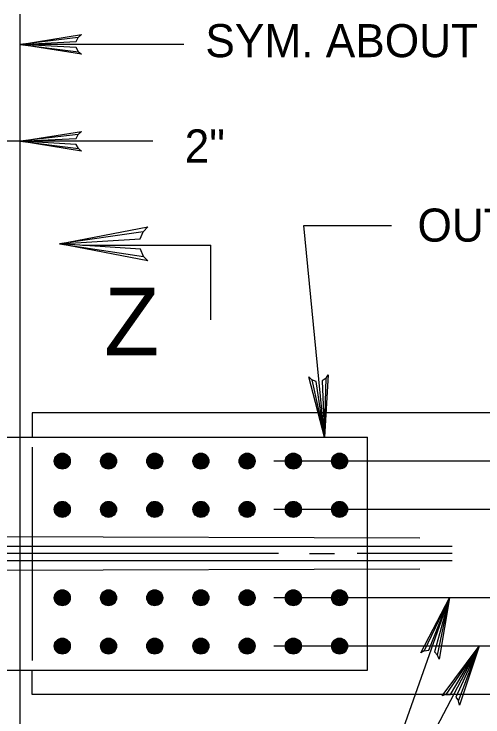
# Model space of a CAD drawing. Extents: x 638466 to 639375, y 297808 to 298996.
# Drawn here: x 638967.9 to 639013.8, y 298148.9 to 298217.7 of the extents above; entities that cross this region are included whole.
import ezdxf

# ---------------------------------------------------------------- set-up
doc = ezdxf.new("R2010")
doc.units = 0
for name, color, linetype in [('1', 7, 'Continuous'), ('2', 7, 'Continuous'), ('4', 7, 'Continuous')]:
    doc.layers.add(name, color=color, linetype=linetype)

msp = doc.modelspace()

# ---------------------------------------------------------------- linework, layer by layer
at = {"layer": '1'}
for points in [[(638974.195, 298214.016), (638973.983, 298214.43), (638968.473, 298214.736), (638974.195, 298214.016), (638974.487, 298213.764), (638968.473, 298214.736), (638973.977, 298215.006), (638974.179, 298215.415), (638968.473, 298214.736), (638974.487, 298215.69), (638974.179, 298215.415)], [(638974.195, 298204.523), (638973.983, 298204.935), (638968.473, 298205.241), (638974.195, 298204.523), (638974.487, 298204.271), (638968.473, 298205.241), (638973.977, 298205.511), (638974.179, 298205.92), (638968.473, 298205.241), (638974.487, 298206.195), (638974.179, 298205.92)], [(638980.565, 298193.966), (638980.259, 298194.682), (638972.327, 298195.208), (638980.565, 298193.966), (638980.983, 298193.532), (638972.327, 298195.208), (638980.25, 298195.674), (638980.542, 298196.383), (638972.327, 298195.208), (638980.983, 298196.86), (638980.542, 298196.383)], [(638998.452, 298182.043), (638998.058, 298181.791), (638998.286, 298176.279), (638998.452, 298182.043), (638998.673, 298182.358), (638998.286, 298176.279), (638997.485, 298181.733), (638997.059, 298181.893), (638998.286, 298176.279), (638996.758, 298182.174), (638997.059, 298181.893)], [(639008.053, 298155.338), (639008.514, 298155.408), (639010.555, 298160.533), (639008.053, 298155.338), (639007.722, 298155.14), (639010.555, 298160.533), (639009.061, 298155.228), (639009.385, 298154.906), (639010.555, 298160.533), (639009.547, 298154.526), (639009.385, 298154.906)], [(639010.172, 298151.063), (639010.64, 298151.061), (639013.446, 298155.811), (639010.172, 298151.063), (639009.817, 298150.919), (639013.446, 298155.811), (639011.153, 298150.8), (639011.423, 298150.433), (639013.446, 298155.811), (639011.525, 298150.03), (639011.423, 298150.433)]]:
    msp.add_lwpolyline(points, dxfattribs=at)
at = {"layer": '2'}
for p, q in [((638968.473, 298137.466), (638968.473, 298217.701)), ((638969.654, 298178.641), (638969.654, 298176.279)), ((639039.337, 298178.641), (638969.654, 298178.641)), ((638934.694, 298176.279), (639002.527, 298176.279)), ((639002.527, 298153.441), (639002.527, 298176.279)), ((638969.654, 298175.302), (638969.654, 298154.409)), ((639007.648, 298166.377), (638929.301, 298166.624)), ((639010.8, 298165.573), (638925.401, 298165.573)), ((638993.799, 298164.865), (638925.401, 298164.865)), ((638996.821, 298164.865), (638999.294, 298164.865)), ((639010.8, 298164.865), (639001.492, 298164.865)), ((639010.8, 298164.156), (638925.401, 298164.156)), ((639007.648, 298163.352), (638929.301, 298163.103)), ((638934.532, 298153.441), (639002.527, 298153.441)), ((638969.654, 298151.079), (638969.654, 298153.441)), ((639039.337, 298151.079), (638969.654, 298151.079))]:
    msp.add_line(p, q, dxfattribs=at)
for centre, radius in [((638972.612, 298173.919), 0.783), ((638972.612, 298173.919), 0.727), ((638977.138, 298173.919), 0.783), ((638977.138, 298173.919), 0.727), ((638981.665, 298173.919), 0.783), ((638981.665, 298173.919), 0.727), ((638986.191, 298173.919), 0.783), ((638986.191, 298173.919), 0.727), ((638990.721, 298173.919), 0.783), ((638990.721, 298173.919), 0.727), ((638995.248, 298173.919), 0.783), ((638995.248, 298173.919), 0.727), ((638999.774, 298173.919), 0.783), ((638999.774, 298173.919), 0.727), ((638972.612, 298173.919), 0.672), ((638972.612, 298173.919), 0.616), ((638972.612, 298173.919), 0.561), ((638972.612, 298173.919), 0.505), ((638972.612, 298173.919), 0.449), ((638972.612, 298173.919), 0.394), ((638972.612, 298173.919), 0.338), ((638972.612, 298173.919), 0.283), ((638972.612, 298173.919), 0.227), ((638972.612, 298173.919), 0.171), ((638972.612, 298173.919), 0.116), ((638972.612, 298173.919), 0.0601), ((638977.138, 298173.919), 0.672), ((638977.138, 298173.919), 0.616), ((638977.138, 298173.919), 0.561), ((638977.138, 298173.919), 0.505), ((638977.138, 298173.919), 0.449), ((638977.138, 298173.919), 0.394), ((638977.138, 298173.919), 0.338), ((638977.138, 298173.919), 0.283), ((638977.138, 298173.919), 0.227), ((638977.138, 298173.919), 0.171), ((638977.138, 298173.919), 0.116), ((638977.138, 298173.919), 0.0601), ((638981.665, 298173.919), 0.672), ((638981.665, 298173.919), 0.616), ((638981.665, 298173.919), 0.561), ((638981.665, 298173.919), 0.505), ((638981.665, 298173.919), 0.449), ((638981.665, 298173.919), 0.394), ((638981.665, 298173.919), 0.338), ((638981.665, 298173.919), 0.283), ((638981.665, 298173.919), 0.227), ((638981.665, 298173.919), 0.171), ((638981.665, 298173.919), 0.116), ((638981.665, 298173.919), 0.0601), ((638986.191, 298173.919), 0.672), ((638986.191, 298173.919), 0.616), ((638986.191, 298173.919), 0.561), ((638986.191, 298173.919), 0.505), ((638986.191, 298173.919), 0.449), ((638986.191, 298173.919), 0.394), ((638986.191, 298173.919), 0.338), ((638986.191, 298173.919), 0.283), ((638986.191, 298173.919), 0.227), ((638986.191, 298173.919), 0.171), ((638986.191, 298173.919), 0.116), ((638986.191, 298173.919), 0.0601), ((638990.721, 298173.919), 0.672), ((638990.721, 298173.919), 0.616), ((638990.721, 298173.919), 0.561), ((638990.721, 298173.919), 0.505), ((638990.721, 298173.919), 0.449), ((638990.721, 298173.919), 0.394), ((638990.721, 298173.919), 0.338), ((638990.721, 298173.919), 0.283), ((638990.721, 298173.919), 0.227), ((638990.721, 298173.919), 0.171), ((638990.721, 298173.919), 0.116), ((638990.721, 298173.919), 0.0601), ((638995.248, 298173.919), 0.672), ((638995.248, 298173.919), 0.616), ((638995.248, 298173.919), 0.561), ((638995.248, 298173.919), 0.505), ((638995.248, 298173.919), 0.449), ((638995.248, 298173.919), 0.394), ((638995.248, 298173.919), 0.338), ((638995.248, 298173.919), 0.283), ((638995.248, 298173.919), 0.227), ((638995.248, 298173.919), 0.171), ((638995.248, 298173.919), 0.116), ((638995.248, 298173.919), 0.0601), ((638999.774, 298173.919), 0.672), ((638999.774, 298173.919), 0.616), ((638999.774, 298173.919), 0.561), ((638999.774, 298173.919), 0.505), ((638999.774, 298173.919), 0.449), ((638999.774, 298173.919), 0.394), ((638999.774, 298173.919), 0.338), ((638999.774, 298173.919), 0.283), ((638999.774, 298173.919), 0.227), ((638999.774, 298173.919), 0.171), ((638999.774, 298173.919), 0.116), ((638999.774, 298173.919), 0.0601), ((638972.612, 298169.197), 0.783), ((638972.612, 298169.197), 0.727), ((638972.612, 298169.197), 0.672), ((638972.612, 298169.197), 0.616), ((638977.138, 298169.197), 0.783), ((638977.138, 298169.197), 0.727), ((638977.138, 298169.197), 0.672), ((638977.138, 298169.197), 0.616), ((638981.665, 298169.197), 0.783), ((638981.665, 298169.197), 0.727), ((638981.665, 298169.197), 0.672), ((638981.665, 298169.197), 0.616), ((638986.191, 298169.197), 0.783), ((638986.191, 298169.197), 0.727), ((638986.191, 298169.197), 0.672), ((638986.191, 298169.197), 0.616), ((638990.721, 298169.197), 0.783), ((638990.721, 298169.197), 0.727), ((638990.721, 298169.197), 0.672), ((638990.721, 298169.197), 0.616), ((638995.248, 298169.197), 0.783), ((638995.248, 298169.197), 0.727), ((638995.248, 298169.197), 0.672), ((638995.248, 298169.197), 0.616), ((638999.774, 298169.197), 0.783), ((638999.774, 298169.197), 0.727), ((638999.774, 298169.197), 0.672), ((638999.774, 298169.197), 0.616), ((638972.612, 298169.197), 0.561), ((638972.612, 298169.197), 0.505), ((638972.612, 298169.197), 0.449), ((638972.612, 298169.197), 0.394), ((638972.612, 298169.197), 0.338), ((638972.612, 298169.197), 0.283), ((638972.612, 298169.197), 0.227), ((638972.612, 298169.197), 0.171), ((638972.612, 298169.197), 0.116), ((638972.612, 298169.197), 0.0601), ((638977.138, 298169.197), 0.561), ((638977.138, 298169.197), 0.505), ((638977.138, 298169.197), 0.449), ((638977.138, 298169.197), 0.394), ((638977.138, 298169.197), 0.338), ((638977.138, 298169.197), 0.283), ((638977.138, 298169.197), 0.227), ((638977.138, 298169.197), 0.171), ((638977.138, 298169.197), 0.116), ((638977.138, 298169.197), 0.0601), ((638981.665, 298169.197), 0.561), ((638981.665, 298169.197), 0.505), ((638981.665, 298169.197), 0.449), ((638981.665, 298169.197), 0.394), ((638981.665, 298169.197), 0.338), ((638981.665, 298169.197), 0.283), ((638981.665, 298169.197), 0.227), ((638981.665, 298169.197), 0.171), ((638981.665, 298169.197), 0.116), ((638981.665, 298169.197), 0.0601), ((638986.191, 298169.197), 0.561), ((638986.191, 298169.197), 0.505), ((638986.191, 298169.197), 0.449), ((638986.191, 298169.197), 0.394), ((638986.191, 298169.197), 0.338), ((638986.191, 298169.197), 0.283), ((638986.191, 298169.197), 0.227), ((638986.191, 298169.197), 0.171), ((638986.191, 298169.197), 0.116), ((638986.191, 298169.197), 0.0601), ((638990.721, 298169.197), 0.561), ((638990.721, 298169.197), 0.505), ((638990.721, 298169.197), 0.449), ((638990.721, 298169.197), 0.394), ((638990.721, 298169.197), 0.338), ((638990.721, 298169.197), 0.283), ((638990.721, 298169.197), 0.227), ((638990.721, 298169.197), 0.171), ((638990.721, 298169.197), 0.116), ((638990.721, 298169.197), 0.0601), ((638995.248, 298169.197), 0.561), ((638995.248, 298169.197), 0.505), ((638995.248, 298169.197), 0.449), ((638995.248, 298169.197), 0.394), ((638995.248, 298169.197), 0.338), ((638995.248, 298169.197), 0.283), ((638995.248, 298169.197), 0.227), ((638995.248, 298169.197), 0.171), ((638995.248, 298169.197), 0.116), ((638995.248, 298169.197), 0.0601), ((638999.774, 298169.197), 0.561), ((638999.774, 298169.197), 0.505), ((638999.774, 298169.197), 0.449), ((638999.774, 298169.197), 0.394), ((638999.774, 298169.197), 0.338), ((638999.774, 298169.197), 0.283), ((638999.774, 298169.197), 0.227), ((638999.774, 298169.197), 0.171), ((638999.774, 298169.197), 0.116), ((638999.774, 298169.197), 0.0601), ((638972.612, 298160.533), 0.783), ((638972.612, 298160.533), 0.727), ((638972.612, 298160.533), 0.672), ((638972.612, 298160.533), 0.616), ((638972.612, 298160.533), 0.561), ((638972.612, 298160.533), 0.505), ((638972.612, 298160.533), 0.449), ((638972.612, 298160.533), 0.394), ((638972.612, 298160.533), 0.338), ((638977.138, 298160.533), 0.783), ((638977.138, 298160.533), 0.727), ((638977.138, 298160.533), 0.672), ((638977.138, 298160.533), 0.616), ((638977.138, 298160.533), 0.561), ((638977.138, 298160.533), 0.505), ((638977.138, 298160.533), 0.449), ((638977.138, 298160.533), 0.394), ((638977.138, 298160.533), 0.338), ((638981.665, 298160.533), 0.783), ((638981.665, 298160.533), 0.727), ((638981.665, 298160.533), 0.672), ((638981.665, 298160.533), 0.616), ((638981.665, 298160.533), 0.561), ((638981.665, 298160.533), 0.505), ((638981.665, 298160.533), 0.449), ((638981.665, 298160.533), 0.394), ((638981.665, 298160.533), 0.338), ((638986.191, 298160.533), 0.783), ((638986.191, 298160.533), 0.727), ((638986.191, 298160.533), 0.672), ((638986.191, 298160.533), 0.616), ((638986.191, 298160.533), 0.561), ((638986.191, 298160.533), 0.505), ((638986.191, 298160.533), 0.449), ((638986.191, 298160.533), 0.394), ((638986.191, 298160.533), 0.338), ((638990.721, 298160.533), 0.783), ((638990.721, 298160.533), 0.727), ((638990.721, 298160.533), 0.672), ((638990.721, 298160.533), 0.616), ((638990.721, 298160.533), 0.561), ((638990.721, 298160.533), 0.505), ((638990.721, 298160.533), 0.449), ((638990.721, 298160.533), 0.394), ((638990.721, 298160.533), 0.338), ((638995.248, 298160.533), 0.783), ((638995.248, 298160.533), 0.727), ((638995.248, 298160.533), 0.672), ((638995.248, 298160.533), 0.616), ((638995.248, 298160.533), 0.561), ((638995.248, 298160.533), 0.505), ((638995.248, 298160.533), 0.449), ((638995.248, 298160.533), 0.394), ((638995.248, 298160.533), 0.338), ((638999.774, 298160.533), 0.783), ((638999.774, 298160.533), 0.727), ((638999.774, 298160.533), 0.672), ((638999.774, 298160.533), 0.616), ((638999.774, 298160.533), 0.561), ((638999.774, 298160.533), 0.505), ((638999.774, 298160.533), 0.449), ((638999.774, 298160.533), 0.394), ((638999.774, 298160.533), 0.338), ((638972.612, 298160.533), 0.283), ((638972.612, 298160.533), 0.227), ((638972.612, 298160.533), 0.171), ((638972.612, 298160.533), 0.116), ((638972.612, 298160.533), 0.0601), ((638977.138, 298160.533), 0.283), ((638977.138, 298160.533), 0.227), ((638977.138, 298160.533), 0.171), ((638977.138, 298160.533), 0.116), ((638977.138, 298160.533), 0.0601), ((638981.665, 298160.533), 0.283), ((638981.665, 298160.533), 0.227), ((638981.665, 298160.533), 0.171), ((638981.665, 298160.533), 0.116), ((638981.665, 298160.533), 0.0601), ((638986.191, 298160.533), 0.283), ((638986.191, 298160.533), 0.227), ((638986.191, 298160.533), 0.171), ((638986.191, 298160.533), 0.116), ((638986.191, 298160.533), 0.0601), ((638990.721, 298160.533), 0.283), ((638990.721, 298160.533), 0.227), ((638990.721, 298160.533), 0.171), ((638990.721, 298160.533), 0.116), ((638990.721, 298160.533), 0.0601), ((638995.248, 298160.533), 0.283), ((638995.248, 298160.533), 0.227), ((638995.248, 298160.533), 0.171), ((638995.248, 298160.533), 0.116), ((638995.248, 298160.533), 0.0601), ((638999.774, 298160.533), 0.283), ((638999.774, 298160.533), 0.227), ((638999.774, 298160.533), 0.171), ((638999.774, 298160.533), 0.116), ((638999.774, 298160.533), 0.0601), ((638972.612, 298155.811), 0.783), ((638972.612, 298155.811), 0.727), ((638972.612, 298155.811), 0.672), ((638972.612, 298155.811), 0.616), ((638972.612, 298155.811), 0.561), ((638972.612, 298155.811), 0.505), ((638972.612, 298155.811), 0.449), ((638972.612, 298155.811), 0.394), ((638972.612, 298155.811), 0.338), ((638972.612, 298155.811), 0.283), ((638972.612, 298155.811), 0.227), ((638977.138, 298155.811), 0.783), ((638977.138, 298155.811), 0.727), ((638977.138, 298155.811), 0.672), ((638977.138, 298155.811), 0.616), ((638977.138, 298155.811), 0.561), ((638977.138, 298155.811), 0.505), ((638977.138, 298155.811), 0.449), ((638977.138, 298155.811), 0.394), ((638977.138, 298155.811), 0.338), ((638977.138, 298155.811), 0.283), ((638977.138, 298155.811), 0.227), ((638981.665, 298155.811), 0.783), ((638981.665, 298155.811), 0.727), ((638981.665, 298155.811), 0.672), ((638981.665, 298155.811), 0.616), ((638981.665, 298155.811), 0.561), ((638981.665, 298155.811), 0.505), ((638981.665, 298155.811), 0.449), ((638981.665, 298155.811), 0.394), ((638981.665, 298155.811), 0.338), ((638981.665, 298155.811), 0.283), ((638981.665, 298155.811), 0.227), ((638986.191, 298155.811), 0.783), ((638986.191, 298155.811), 0.727), ((638986.191, 298155.811), 0.672), ((638986.191, 298155.811), 0.616), ((638986.191, 298155.811), 0.561), ((638986.191, 298155.811), 0.505), ((638986.191, 298155.811), 0.449), ((638986.191, 298155.811), 0.394), ((638986.191, 298155.811), 0.338), ((638986.191, 298155.811), 0.283), ((638986.191, 298155.811), 0.227), ((638990.721, 298155.811), 0.783), ((638990.721, 298155.811), 0.727), ((638990.721, 298155.811), 0.672), ((638990.721, 298155.811), 0.616), ((638990.721, 298155.811), 0.561), ((638990.721, 298155.811), 0.505), ((638990.721, 298155.811), 0.449), ((638990.721, 298155.811), 0.394), ((638990.721, 298155.811), 0.338), ((638990.721, 298155.811), 0.283), ((638990.721, 298155.811), 0.227), ((638995.248, 298155.811), 0.783), ((638995.248, 298155.811), 0.727), ((638995.248, 298155.811), 0.672), ((638995.248, 298155.811), 0.616), ((638995.248, 298155.811), 0.561), ((638995.248, 298155.811), 0.505), ((638995.248, 298155.811), 0.449), ((638995.248, 298155.811), 0.394), ((638995.248, 298155.811), 0.338), ((638995.248, 298155.811), 0.283), ((638995.248, 298155.811), 0.227), ((638999.774, 298155.811), 0.783), ((638999.774, 298155.811), 0.727), ((638999.774, 298155.811), 0.672), ((638999.774, 298155.811), 0.616), ((638999.774, 298155.811), 0.561), ((638999.774, 298155.811), 0.505), ((638999.774, 298155.811), 0.449), ((638999.774, 298155.811), 0.394), ((638999.774, 298155.811), 0.338), ((638999.774, 298155.811), 0.283), ((638999.774, 298155.811), 0.227), ((638972.612, 298155.811), 0.171), ((638972.612, 298155.811), 0.116), ((638972.612, 298155.811), 0.0601), ((638977.138, 298155.811), 0.171), ((638977.138, 298155.811), 0.116), ((638977.138, 298155.811), 0.0601), ((638981.665, 298155.811), 0.171), ((638981.665, 298155.811), 0.116), ((638981.665, 298155.811), 0.0601), ((638986.191, 298155.811), 0.171), ((638986.191, 298155.811), 0.116), ((638986.191, 298155.811), 0.0601), ((638990.721, 298155.811), 0.171), ((638990.721, 298155.811), 0.116), ((638990.721, 298155.811), 0.0601), ((638995.248, 298155.811), 0.171), ((638995.248, 298155.811), 0.116), ((638995.248, 298155.811), 0.0601), ((638999.774, 298155.811), 0.171), ((638999.774, 298155.811), 0.116), ((638999.774, 298155.811), 0.0601)]:
    msp.add_circle(centre, radius, dxfattribs=at)
at = {"layer": '4'}
for p, q in [((638984.513, 298214.736), (638968.473, 298214.736)), ((638981.496, 298205.241), (638937.176, 298205.241)), ((638996.288, 298196.995), (639004.856, 298196.995)), ((638998.286, 298176.279), (638996.288, 298196.995)), ((638974.602, 298195.064), (638987.168, 298195.064)), ((638987.168, 298187.742), (638987.168, 298195.064)), ((639021.65, 298173.916), (638993.333, 298173.916)), ((639021.65, 298169.196), (638993.333, 298169.196)), ((639021.65, 298160.533), (638993.333, 298160.533)), ((638999.332, 298128.889), (639010.555, 298160.533)), ((639021.65, 298155.811), (638993.333, 298155.811)), ((638999.332, 298128.889), (639013.446, 298155.811))]:
    msp.add_line(p, q, dxfattribs=at)

# ---------------------------------------------------------------- texts
for s, height, p in [('SYM. ABOUT L SPLICE', 3.24005, (638986.626, 298213.478)), ('2"', 3.24, (638984.599, 298203.164)), ('OUTSIDE SPLICE PLATE', 3.24004, (639007.412, 298195.413)), ('Z', 6.615, (638976.704, 298184.289))]:
    msp.add_text(s, height=height, dxfattribs=at).set_placement(p)

doc.saveas('drawing.dxf')
